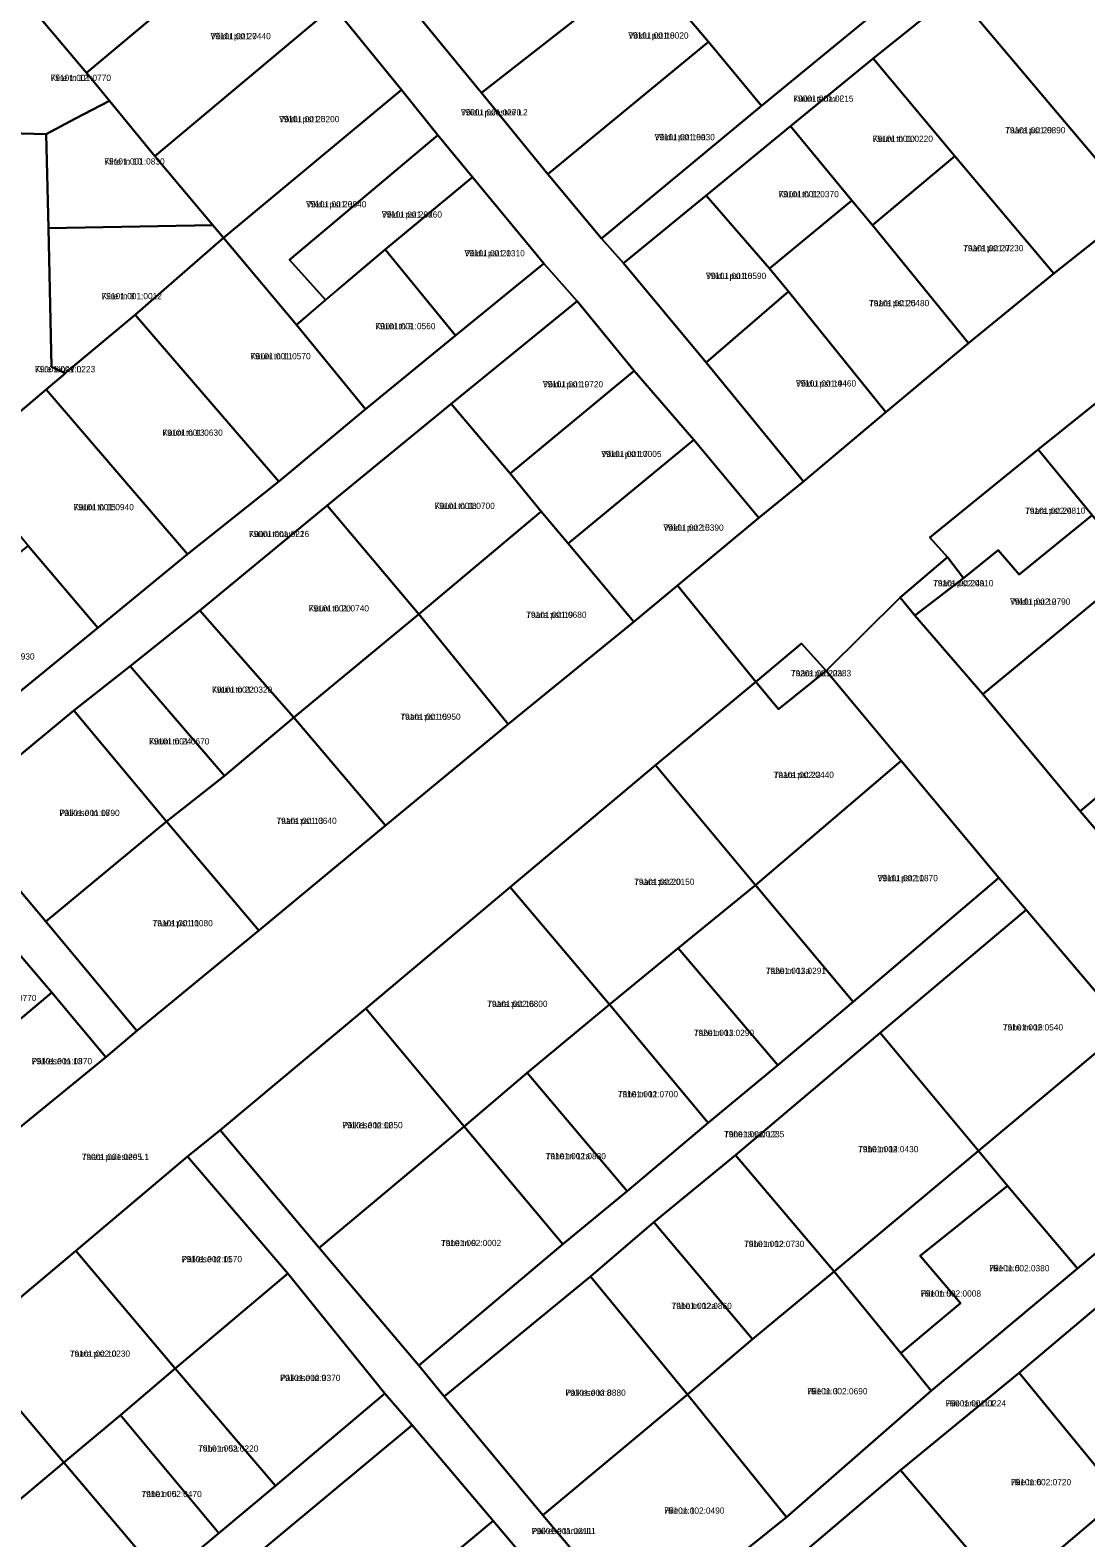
# Model space of a CAD drawing. Extents: x 587616 to 632239, y 6547421 to 6574977.
# Drawn here: x 611517.4 to 611771.3, y 6571731.9 to 6572094.4 of the extents above; entities that cross this region are included whole.
import ezdxf

# ---------------------------------------------------------------- set-up
doc = ezdxf.new("R2010")
doc.units = 0
for name, color, linetype in [('L_AADRESS', 7, 'Continuous'), ('PIIR', 7, 'Continuous'), ('TUNNUS', 7, 'Continuous')]:
    doc.layers.add(name, color=color, linetype=linetype)

msp = doc.modelspace()

# ---------------------------------------------------------------- linework, layer by layer
at = {"layer": 'PIIR'}
for points in [[(611734.61, 6572140.41), (611738.29, 6572189.62), (611746.94, 6572191.35), (611745.11, 6572168.19), (611742.87, 6572141.29), (611739.89, 6572103.61), (611720.1, 6572087.66), (611700.19, 6572071.38), (611679.96, 6572054.69), (611660.05, 6572038.44), (611654.81, 6572044.31), (611693.23, 6572076.25), (611732.06, 6572108.11)], [(611703.36, 6571985.87), (611692.63, 6571977.17), (611676.94, 6571995.95), (611662.62, 6572012.53), (611648.93, 6572029.28), (611640.94, 6572038.35), (611623.77, 6572059.08), (611615.42, 6572069.17), (611606.67, 6572080.06), (611590.29, 6572100.13), (611574.15, 6572120.39), (611557.93, 6572140.36), (611538.56, 6572163.58), (611547.62, 6572175.56), (611567.27, 6572151.15), (611582.31, 6572132.43), (611591.11, 6572121.71), (611608.5, 6572100.53), (611625.91, 6572079.36), (611641.9, 6572059.83), (611654.81, 6572044.31), (611660.05, 6572038.44), (611679.91, 6572014.55)], [(611514.35, 6572103.88), (611557.93, 6572140.36), (611574.15, 6572120.39), (611530.95, 6572084.21)], [(611706.64, 6572134.83), (611705.65, 6572123.76), (611732.06, 6572108.11), (611693.23, 6572076.25), (611680.48, 6572091.65), (611664.95, 6572109.99), (611697.2, 6572133.09)], [(611625.91, 6572079.36), (611657.01, 6572103.71), (611644.26, 6572119.39), (611652.41, 6572124.99), (611664.95, 6572109.99), (611680.48, 6572091.65), (611641.9, 6572059.83)], [(611536.45, 6572077.46), (611530.95, 6572084.21), (611574.15, 6572120.39), (611590.29, 6572100.13), (611547.36, 6572064.13)], [(611625.89, 6572114.56), (611629.79, 6572109.4), (611644.26, 6572119.39), (611657.01, 6572103.71), (611625.91, 6572079.36), (611608.5, 6572100.53)], [(611739.89, 6572103.61), (611762.77, 6572112.21), (611766.36, 6572113.68), (611803.38, 6572068.18), (611783.59, 6572051.79)], [(611514.35, 6572103.88), (611530.95, 6572084.21), (611536.45, 6572077.46), (611528.14, 6572073.14), (611521.21, 6572069.41), (611509.45, 6572069.74), (611508.95, 6572086.97), (611508.16, 6572110.87)], [(611720.1, 6572087.66), (611739.89, 6572103.61), (611783.59, 6572051.79), (611763.57, 6572035.93), (611739.79, 6572064.13)], [(611561.26, 6572047.51), (611547.36, 6572064.13), (611590.29, 6572100.13), (611606.67, 6572080.06), (611563.83, 6572044.49)], [(611680.48, 6572091.65), (611693.23, 6572076.25), (611654.81, 6572044.31), (611641.9, 6572059.83)], [(611739.79, 6572064.13), (611719.93, 6572047.53), (611715.01, 6572053.46), (611700.19, 6572071.38), (611720.1, 6572087.66)], [(611588.41, 6572029.56), (611581.39, 6572023.6), (611563.83, 6572044.49), (611606.67, 6572080.06), (611615.42, 6572069.17), (611579.71, 6572039.21)], [(611521.21, 6572069.41), (611528.14, 6572073.14), (611536.45, 6572077.46), (611547.36, 6572064.13), (611561.26, 6572047.51), (611521.78, 6572046.81)], [(611679.96, 6572054.69), (611700.19, 6572071.38), (611715.01, 6572053.46), (611695.16, 6572037.15)], [(611509.8, 6572062.8), (611509.45, 6572069.74), (611521.21, 6572069.41), (611521.78, 6572046.81), (611522.49, 6572013.48), (611525.86, 6572011.98), (611521.23, 6572008.07), (611500.42, 6571990.5), (611457.96, 6571954.63), (611453.96, 6571959.31), (611458.08, 6571984.75), (611480.63, 6571984.97), (611487.68, 6571990.93), (611511.65, 6572011.07), (611510.65, 6572038.95)], [(611594.44, 6572034.67), (611588.41, 6572029.56), (611579.71, 6572039.21), (611615.42, 6572069.17), (611623.77, 6572059.08), (611602.76, 6572041.72)], [(611739.79, 6572064.13), (611763.57, 6572035.93), (611743.05, 6572019.15), (611719.93, 6572047.53)], [(611619.63, 6572021.02), (611602.76, 6572041.72), (611623.77, 6572059.08), (611640.94, 6572038.35)], [(611769.9, 6571906.6), (611806.53, 6571937.26), (611843.41, 6571968.2), (611880.59, 6571998.73), (611918.86, 6572031.13), (611952.43, 6572060.06), (611959.53, 6572054.37), (611924.27, 6572023.59), (611897.13, 6572000.36), (611866.46, 6571974.8), (611836.15, 6571948.55), (611805.37, 6571923.25), (611776.48, 6571898.9)], [(611679.96, 6572054.69), (611695.16, 6572037.15), (611699.73, 6572031.59), (611679.91, 6572014.55), (611660.05, 6572038.44)], [(611695.16, 6572037.15), (611715.01, 6572053.46), (611719.93, 6572047.53), (611743.05, 6572019.15), (611723.13, 6572002.62), (611699.73, 6572031.59)], [(611561.26, 6572047.51), (611563.83, 6572044.49), (611542.61, 6572025.95), (611526.3, 6572012.36), (611525.86, 6572011.98), (611522.49, 6572013.48), (611521.78, 6572046.81)], [(611563.83, 6572044.49), (611581.39, 6572023.6), (611598.02, 6572003.32), (611577.14, 6571985.89), (611542.61, 6572025.95)], [(611581.39, 6572023.6), (611594.44, 6572034.67), (611602.76, 6572041.72), (611619.63, 6572021.02), (611598.02, 6572003.32)], [(611619.63, 6572021.02), (611640.94, 6572038.35), (611648.93, 6572029.28), (611618.64, 6572004.59), (611588.82, 6571980.13), (611558.21, 6571954.88), (611541.38, 6571941.51), (611527.85, 6571930.86), (611498.67, 6571906.72), (611490.78, 6571915.71), (611533.66, 6571950.72), (611555.19, 6571968.47), (611577.14, 6571985.89), (611598.02, 6572003.32)], [(611699.73, 6572031.59), (611723.13, 6572002.62), (611703.36, 6571985.87), (611679.91, 6572014.55)], [(611648.93, 6572029.28), (611662.62, 6572012.53), (611632.78, 6571987.83), (611618.64, 6572004.59)], [(611526.3, 6572012.36), (611542.61, 6572025.95), (611577.14, 6571985.89), (611555.19, 6571968.47), (611521.23, 6572008.07), (611525.86, 6572011.98)], [(611772.8, 6571977.8), (611759.8, 6571993.57), (611797.19, 6572023.62), (611820.25, 6571995.62), (611783.26, 6571965.15)], [(611662.62, 6572012.53), (611676.94, 6571995.95), (611646.72, 6571971.02), (611640.24, 6571978.66), (611632.78, 6571987.83)], [(611500.42, 6571990.5), (611521.23, 6572008.07), (611555.19, 6571968.47), (611533.66, 6571950.72), (611516.87, 6571970.44)], [(611588.82, 6571980.13), (611618.64, 6572004.59), (611632.78, 6571987.83), (611640.24, 6571978.66), (611610.83, 6571954.01)], [(611676.94, 6571995.95), (611692.63, 6571977.17), (611673.02, 6571960.92), (611662.57, 6571952.19), (611646.72, 6571971.02)], [(611750.19, 6571969.42), (611741.85, 6571962.69), (611737.99, 6571967.74), (611733.73, 6571972.44), (611759.8, 6571993.57), (611772.8, 6571977.8), (611755.24, 6571963.55)], [(611558.21, 6571954.88), (611588.82, 6571980.13), (611610.83, 6571954.01), (611580.76, 6571929.17)], [(611610.83, 6571954.01), (611640.24, 6571978.66), (611646.72, 6571971.02), (611662.57, 6571952.19), (611632.36, 6571927.58)], [(611730.17, 6571953.67), (611741.85, 6571962.69), (611750.19, 6571969.42), (611755.24, 6571963.55), (611772.8, 6571977.8), (611783.26, 6571965.15), (611746.45, 6571934.76)], [(611474.34, 6571935.26), (611478.02, 6571938.23), (611484.06, 6571943.51), (611488.26, 6571946.91), (611491.72, 6571949.74), (611516.87, 6571970.44), (611533.66, 6571950.72), (611490.78, 6571915.71)], [(611737.99, 6571967.74), (611741.85, 6571962.69), (611730.17, 6571953.67), (611726.63, 6571958.04)], [(611806.53, 6571937.26), (611769.9, 6571906.6), (611746.45, 6571934.76), (611783.26, 6571965.15)], [(611708.77, 6571940.38), (611726.63, 6571958.04), (611730.17, 6571953.67), (611746.45, 6571934.76), (611769.9, 6571906.6), (611776.48, 6571898.9), (611800.04, 6571870.66), (611814.69, 6571853.27), (611817.51, 6571849.51), (611818.84, 6571847.89), (611824.09, 6571842.08), (611829.43, 6571833.8), (611854.54, 6571803.96), (611879.78, 6571774.07), (611860.7, 6571758.31), (611835.77, 6571788.31), (611810.91, 6571818.25), (611804.56, 6571826.12), (611780.93, 6571854.58), (611756.87, 6571882.88), (611750.35, 6571890.57), (611726.84, 6571918.76)], [(611564.07, 6571915.09), (611541.38, 6571941.51), (611558.21, 6571954.88), (611580.76, 6571929.17)], [(611580.76, 6571929.17), (611610.83, 6571954.01), (611632.36, 6571927.58), (611602.84, 6571903.18)], [(611691.91, 6571937.71), (611702.84, 6571946.96), (611708.77, 6571940.38), (611697.31, 6571931.16)], [(611541.38, 6571941.51), (611564.07, 6571915.09), (611550.17, 6571904.12), (611527.85, 6571930.86)], [(611667.8, 6571917.67), (611691.91, 6571937.71), (611697.31, 6571931.16), (611708.77, 6571940.38), (611726.84, 6571918.76), (611691.81, 6571888.85)], [(611498.67, 6571906.72), (611527.85, 6571930.86), (611550.17, 6571904.12), (611521.13, 6571880.06)], [(611550.17, 6571904.12), (611564.07, 6571915.09), (611580.76, 6571929.17), (611602.84, 6571903.18), (611572.35, 6571877.96)], [(611667.8, 6571917.67), (611691.81, 6571888.85), (611673.23, 6571873.7), (611656.7, 6571860.15), (611632.8, 6571888.33)], [(611691.81, 6571888.85), (611726.84, 6571918.76), (611750.35, 6571890.57), (611715.31, 6571860.82)], [(611521.13, 6571880.06), (611550.17, 6571904.12), (611572.35, 6571877.96), (611543.01, 6571853.78)], [(611616.93, 6571765.84), (611610.82, 6571773.32), (611645.46, 6571802.49), (611660.91, 6571815.22), (611680.42, 6571831.65), (611697.21, 6571845.59), (611715.31, 6571860.82), (611750.35, 6571890.57), (611756.87, 6571882.88), (611721.77, 6571853.32), (611687.04, 6571823.89), (611667.39, 6571807.77), (611652.09, 6571794.76)], [(611598.11, 6571859.14), (611632.8, 6571888.33), (611656.7, 6571860.15), (611636.93, 6571843.69), (611621.75, 6571830.77)], [(611697.21, 6571845.59), (611673.23, 6571873.7), (611691.81, 6571888.85), (611715.31, 6571860.82)], [(611721.77, 6571853.32), (611756.87, 6571882.88), (611780.93, 6571854.58), (611745.41, 6571824.92)], [(611486.49, 6571859.2), (611509.62, 6571878.21), (611522.57, 6571862.99), (611499.56, 6571843.7), (611492.89, 6571851.4), (611487.85, 6571847.3), (611481.6, 6571855.29)], [(611680.42, 6571831.65), (611656.7, 6571860.15), (611673.23, 6571873.7), (611697.21, 6571845.59)], [(611499.56, 6571843.7), (611522.57, 6571862.99), (611535.53, 6571847.46), (611512.43, 6571828.55)], [(611621.75, 6571830.77), (611586.85, 6571801.61), (611563.05, 6571829.89), (611598.11, 6571859.14)], [(611656.7, 6571860.15), (611680.42, 6571831.65), (611660.91, 6571815.22), (611636.93, 6571843.69)], [(611752.39, 6571816.53), (611745.41, 6571824.92), (611780.93, 6571854.58), (611804.56, 6571826.12), (611769.24, 6571796.62)], [(611710.71, 6571795.93), (611687.04, 6571823.89), (611721.77, 6571853.32), (611745.41, 6571824.92)], [(611636.93, 6571843.69), (611660.91, 6571815.22), (611645.46, 6571802.49), (611621.75, 6571830.77)], [(611713.77, 6571634.95), (611671.25, 6571685.43), (611650, 6571710.77), (611628.75, 6571735.95), (611609.2, 6571759), (611602.7, 6571766.58), (611579.32, 6571795.43), (611555.18, 6571823.56), (611563.05, 6571829.89), (611586.85, 6571801.61), (611610.82, 6571773.32), (611616.93, 6571765.84), (611640.68, 6571737.33), (611664.57, 6571708.99), (611670.97, 6571700.83), (611696.31, 6571671.43), (611720.8, 6571640.41)], [(611610.82, 6571773.32), (611586.85, 6571801.61), (611621.75, 6571830.77), (611645.46, 6571802.49)], [(611664.57, 6571708.99), (611699.25, 6571736.86), (611734.05, 6571767.26), (611769.24, 6571796.62), (611804.56, 6571826.12), (611810.91, 6571818.25), (611782.88, 6571794.92), (611755.22, 6571771.53), (611726.68, 6571748.18), (611699.01, 6571724.71), (611670.97, 6571700.83)], [(611745.41, 6571824.92), (611752.39, 6571816.53), (611731.4, 6571799.7), (611741.14, 6571788.31), (611726.8, 6571776.3), (611710.71, 6571795.93)], [(611528.32, 6571800.92), (611555.18, 6571823.56), (611579.32, 6571795.43), (611552.25, 6571772.58)], [(611667.39, 6571807.77), (611687.04, 6571823.89), (611710.71, 6571795.93), (611691.12, 6571779.67)], [(611769.24, 6571796.62), (611734.05, 6571767.26), (611726.8, 6571776.3), (611741.14, 6571788.31), (611731.4, 6571799.7), (611752.39, 6571816.53)], [(611667.39, 6571807.77), (611691.12, 6571779.67), (611675.43, 6571766.39), (611652.09, 6571794.76)], [(611539.08, 6571761.41), (611525.48, 6571749.97), (611501.52, 6571778.34), (611528.32, 6571800.92), (611552.25, 6571772.58)], [(611675.43, 6571766.39), (611691.12, 6571779.67), (611710.71, 6571795.93), (611726.8, 6571776.3), (611734.05, 6571767.26), (611699.25, 6571736.86)], [(611579.32, 6571795.43), (611602.7, 6571766.58), (611576.4, 6571744.42), (611552.25, 6571772.58)], [(611616.93, 6571765.84), (611652.09, 6571794.76), (611675.43, 6571766.39), (611640.68, 6571737.33)], [(611782.88, 6571794.92), (611808.32, 6571765.1), (611779.77, 6571741.66), (611755.22, 6571771.53)], [(611835.77, 6571788.31), (611860.7, 6571758.31), (611776.98, 6571688.32), (611752.16, 6571718.25), (611779.77, 6571741.66), (611808.32, 6571765.1)], [(611475.22, 6571756.23), (611501.52, 6571778.34), (611525.48, 6571749.97), (611498.55, 6571727.41)], [(611552.25, 6571772.58), (611576.4, 6571744.42), (611562.77, 6571733), (611539.08, 6571761.41)], [(611726.68, 6571748.18), (611755.22, 6571771.53), (611779.77, 6571741.66), (611752.16, 6571718.25)], [(611482.43, 6571652.66), (611482.5, 6571647.61), (611467.85, 6571653.71), (611495.88, 6571677.1), (611522.47, 6571699.21), (611549.36, 6571721.82), (611562.77, 6571733), (611576.4, 6571744.42), (611602.7, 6571766.58), (611609.2, 6571759), (611566.71, 6571723.63), (611537.62, 6571699.64), (611509.76, 6571676.11), (611486.04, 6571655.92)], [(611640.68, 6571737.33), (611675.43, 6571766.39), (611699.25, 6571736.86), (611664.57, 6571708.99)], [(611539.08, 6571761.41), (611562.77, 6571733), (611549.36, 6571721.82), (611525.48, 6571749.97)], [(611566.71, 6571723.63), (611609.2, 6571759), (611628.75, 6571735.95), (611586.2, 6571700.5)], [(611522.47, 6571699.21), (611498.55, 6571727.41), (611525.48, 6571749.97), (611549.36, 6571721.82)], [(611699.01, 6571724.71), (611726.68, 6571748.18), (611752.16, 6571718.25), (611723.93, 6571695.34)], [(611586.2, 6571700.5), (611628.75, 6571735.95), (611650, 6571710.77), (611607.39, 6571675.16)]]:
    msp.add_lwpolyline(points, close=True, dxfattribs=at)
for points in [[(611797.19, 6572023.62), (611759.8, 6571993.57), (611733.73, 6571972.44), (611737.99, 6571967.74), (611726.63, 6571958.04), (611708.77, 6571940.38), (611702.84, 6571946.96), (611691.91, 6571937.71), (611673.02, 6571960.92), (611692.63, 6571977.17), (611703.36, 6571985.87), (611723.13, 6572002.62), (611743.05, 6572019.15), (611763.57, 6572035.93), (611783.59, 6572051.79)], [(611350.81, 6571692.38), (611434.88, 6571762.6), (611442.6, 6571771.6), (611465.95, 6571790.44), (611488.89, 6571809.32), (611512.43, 6571828.55), (611535.53, 6571847.46), (611543.01, 6571853.78), (611572.35, 6571877.96), (611602.84, 6571903.18), (611632.36, 6571927.58), (611662.57, 6571952.19), (611673.02, 6571960.92), (611691.91, 6571937.71), (611667.8, 6571917.67), (611632.8, 6571888.33), (611598.11, 6571859.14), (611563.05, 6571829.89), (611555.18, 6571823.56), (611528.32, 6571800.92), (611501.52, 6571778.34), (611475.22, 6571756.23), (611460.84, 6571744.72), (611438.7, 6571726.29)], [(611498.67, 6571906.72), (611521.13, 6571880.06), (611543.01, 6571853.78), (611535.53, 6571847.46), (611522.57, 6571862.99), (611509.62, 6571878.21)]]:
    msp.add_lwpolyline(points, dxfattribs=at)

# ---------------------------------------------------------------- texts
at = {"layer": 'L_AADRESS'}
for s, p in [('Võidu pst 27', (611560.73, 6572092.26)), ('Võidu pst 18', (611661.21, 6572092.41)), ('Kiire tn 12', (611522.3, 6572082.23)), ('Küüni tänav L1', (611700.88, 6572077.23)), ('Võidu puiestee L2', (611620.96, 6572073.93)), ('Võidu pst 25', (611577.23, 6572072.31)), ('Võidu pst 18a', (611667.53, 6572067.98)), ('Küüni tn 10', (611719.99, 6572067.58)), ('Taara pst 29', (611751.85, 6572069.63)), ('Kiire tn 10', (611535.21, 6572062.13)), ('Võidu pst 23', (611583.71, 6572051.83)), ('Küüni tn 12', (611697.34, 6572054.26)), ('Võidu pst 23a', (611601.91, 6572049.37)), ('Taara pst 27', (611741.75, 6572041.28)), ('Võidu pst 21', (611621.83, 6572040.05)), ('Võidu pst 16', (611679.89, 6572034.6)), ('Kiire tn 8', (611534.55, 6572029.75)), ('Taara pst 25', (611719.1, 6572028.06)), ('Küüni tn 9', (611600.34, 6572022.52)), ('Kiire tänav L2', (611518.5, 6572012.18)), ('Küüni tn 11', (611570.32, 6572015.29)), ('Võidu pst 19', (611640.66, 6572008.55)), ('Võidu pst 14', (611701.52, 6572008.75)), ('Küüni tn 13', (611549.18, 6571996.9)), ('Võidu pst 17', (611654.71, 6571991.78)), ('Küüni tn 18', (611614.62, 6571979.3)), ('Küüni tn 15', (611527.8, 6571979)), ('Taara pst 24', (611756.64, 6571978.13)), ('Küüni tänav L2', (611569.96, 6571972.54)), ('Võidu pst 15', (611669.65, 6571974.07)), ('Taara pst 24a', (611734.52, 6571960.71)), ('Küüni tn 20', (611584.35, 6571954.65)), ('Võidu pst 12', (611753.03, 6571956.28)), ('Taara pst 19', (611636.67, 6571953.12)), ('Taara pst 22a', (611700.32, 6571939.06)), ('Küüni tn 22', (611561.07, 6571935.1)), ('Taara pst 15', (611606.39, 6571928.6)), ('Küüni tn 24', (611545.96, 6571922.67)), ('Taara pst 22', (611696.17, 6571914.62)), ('Päikese tn 16', (611524.39, 6571905.46)), ('Taara pst 13', (611576.58, 6571903.57)), ('Taara pst 20', (611662.63, 6571888.91)), ('Võidu pst 11', (611721.17, 6571889.79)), ('Taara pst 11', (611546.78, 6571878.95)), ('Tähe tn 13a', (611694.27, 6571867.48)), ('Taara pst 16', (611627.29, 6571859.55)), ('Tähe tn 13', (611676.96, 6571852.57)), ('Tähe tn 16', (611751.29, 6571853.9)), ('Päikese tn 13', (611517.75, 6571845.77)), ('Tähe tn 11', (611658.68, 6571837.83)), ('Päikese tn 12', (611592.45, 6571830.38)), ('Tähe tänav L2', (611684.23, 6571828.21)), ('Tähe tn 14', (611716.48, 6571824.62)), ('Taara puiestee L1', (611529.77, 6571822.75)), ('Tähe tn 11a', (611641.33, 6571822.94)), ('Tähe tn 9', (611616.15, 6571802.04)), ('Tähe tn 12', (611689.05, 6571801.82)), ('Päikese tn 11', (611553.82, 6571798.16)), ('Hiie tn 5', (611748.02, 6571795.97)), ('Hiie tn 5a', (611731.55, 6571789.9)), ('Tähe tn 12a', (611671.61, 6571786.91)), ('Taara pst 10', (611526.89, 6571775.43)), ('Päikese tn 9', (611577.48, 6571769.6)), ('Päikese tn 8', (611646.1, 6571766.04)), ('Hiie tn 3', (611704.25, 6571766.4)), ('Hiie tänav L1', (611737.55, 6571763.48)), ('Tähe tn 5a', (611557.74, 6571752.61)), ('Hiie tn 6', (611753.23, 6571744.53)), ('Tähe tn 5', (611544.12, 6571741.68)), ('Hiie tn 1', (611669.85, 6571737.69)), ('Päikese tänav L1', (611637.99, 6571732.78))]:
    msp.add_text(s, height=1.5, dxfattribs=at).set_placement(p)
at = {"layer": 'TUNNUS'}
for s, p in [('79101:001:0440', (611560.73, 6572092.26)), ('79101:001:0020', (611661.21, 6572092.41)), ('79101:001:0770', (611522.3, 6572082.23)), ('79001:001:0215', (611700.88, 6572077.23)), ('79001:001:0270', (611620.96, 6572073.93)), ('79101:001:0200', (611577.23, 6572072.31)), ('79101:001:0030', (611667.53, 6572067.98)), ('79101:001:0220', (611719.99, 6572067.58)), ('79101:001:0890', (611751.85, 6572069.63)), ('79101:001:0830', (611535.21, 6572062.13)), ('79101:001:0840', (611583.71, 6572051.83)), ('79101:001:0370', (611697.34, 6572054.26)), ('79101:001:0760', (611601.91, 6572049.37)), ('79101:001:0230', (611741.75, 6572041.28)), ('79101:001:0310', (611621.83, 6572040.05)), ('79101:001:0590', (611679.89, 6572034.6)), ('79101:001:0012', (611534.55, 6572029.75)), ('79101:001:0480', (611719.1, 6572028.06)), ('79101:001:0560', (611600.34, 6572022.52)), ('79001:001:0223', (611518.5, 6572012.18)), ('79101:001:0570', (611570.32, 6572015.29)), ('79101:001:0720', (611640.66, 6572008.55)), ('79101:001:0460', (611701.52, 6572008.75)), ('79101:001:0630', (611549.18, 6571996.9)), ('79101:001:0005', (611654.71, 6571991.78)), ('79101:001:0700', (611614.62, 6571979.3)), ('79101:001:0940', (611527.8, 6571979)), ('79101:002:0810', (611756.64, 6571978.13)), ('79001:001:0216', (611569.96, 6571972.54)), ('79101:002:0390', (611669.65, 6571974.07)), ('79101:002:0910', (611734.52, 6571960.71)), ('79101:001:0740', (611584.35, 6571954.65)), ('79101:002:0790', (611753.03, 6571956.28)), ('79101:001:0680', (611636.67, 6571953.12)), ('79101:001:0930', (611503.93, 6571943.08)), ('79201:001:0383', (611700.32, 6571939.06)), ('79101:001:0320', (611561.07, 6571935.1)), ('79101:001:0950', (611606.39, 6571928.6)), ('79101:001:0670', (611545.96, 6571922.67)), ('79101:002:0440', (611696.17, 6571914.62)), ('79101:001:0790', (611524.39, 6571905.46)), ('79101:001:0640', (611576.58, 6571903.57)), ('79101:002:0150', (611662.63, 6571888.91)), ('79101:002:0870', (611721.17, 6571889.79)), ('79101:001:0080', (611546.78, 6571878.95)), ('79201:001:0291', (611694.27, 6571867.48)), ('79201:001:0770', (611504.38, 6571860.96)), ('79101:002:0800', (611627.29, 6571859.55)), ('79201:001:0290', (611676.96, 6571852.57)), ('79101:002:0540', (611751.29, 6571853.9)), ('79101:001:0870', (611517.75, 6571845.77)), ('79101:002:0700', (611658.68, 6571837.83)), ('79101:002:0050', (611592.45, 6571830.38)), ('79001:001:0235', (611684.23, 6571828.21)), ('79101:002:0430', (611716.48, 6571824.62)), ('79001:001:0205', (611529.77, 6571822.75)), ('79101:002:0830', (611641.33, 6571822.94)), ('79101:002:0002', (611616.15, 6571802.04)), ('79101:002:0730', (611689.05, 6571801.82)), ('79101:002:0570', (611553.82, 6571798.16)), ('79101:002:0380', (611748.02, 6571795.97)), ('79101:002:0008', (611731.55, 6571789.9)), ('79101:002:0860', (611671.61, 6571786.91)), ('79101:002:0230', (611526.89, 6571775.43)), ('79101:002:0370', (611577.48, 6571769.6)), ('79101:002:0880', (611646.1, 6571766.04)), ('79101:002:0690', (611704.25, 6571766.4)), ('79001:001:0224', (611737.55, 6571763.48)), ('79101:002:0220', (611557.74, 6571752.61)), ('79101:002:0720', (611753.23, 6571744.53)), ('79101:002:0470', (611544.12, 6571741.68)), ('79101:002:0490', (611669.85, 6571737.69)), ('79001:001:0211', (611637.99, 6571732.78))]:
    msp.add_text(s, height=1.5, dxfattribs=at).set_placement(p)

doc.saveas('drawing.dxf')
